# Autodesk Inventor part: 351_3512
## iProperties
Author: tomm
Created: 2002-01
Part Number: 351_3512
Document SubType Name: Sheet Metal
Designer: tomm
Material: Steel, Mild
Control State: 0
Master: False
Checked Out: False
Last Check In Date: 2002-01-29
PropertySet Name: Design Tracking Control
Last Check In By: tomm
Shininess: 70.0
PropertySet Name: _Private Model Information
Density: 7.86
Volume: 2.630878734043038
Area: 27.458653163180035
PropertySet Name: Model Information
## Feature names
1. Base1
2. Bend1
3. Corner Round1
4. Corner Round2
